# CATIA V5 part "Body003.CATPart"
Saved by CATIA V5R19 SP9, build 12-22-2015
Part number: Body003
Definition: design
Nomenclature: Body003
Source: Unknown
Bounding box of the stored display mesh (mm): x -43.94 to -39.44, y -7 to 0, z 15.25 to 25.25
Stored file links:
  Z:\charly_robot\Body003.CATPart
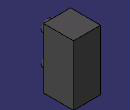
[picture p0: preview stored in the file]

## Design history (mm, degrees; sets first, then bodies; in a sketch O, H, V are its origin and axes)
AxisSystem1: origin (0, 0, 0), X (1, 0, 0), Y (0, 1, 0), Z (0, 0, 1)
Body1 "MANIFOLD_SOLID_BREP #239287" (main body)
  Solid1: solid without history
